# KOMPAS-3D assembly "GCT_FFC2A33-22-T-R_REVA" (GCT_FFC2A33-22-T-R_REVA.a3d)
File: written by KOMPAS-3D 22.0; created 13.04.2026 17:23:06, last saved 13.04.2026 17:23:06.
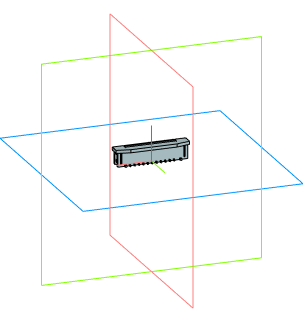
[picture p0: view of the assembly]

Document properties: Автор: Andrey; Полное имя файла: C:\Users\User1\Documents\GCT_FFC2A33-22-T-R_REVA.a3d

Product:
- Component [detail]: 525592253wbm000_01  | qty 1  | source file: 525592253wbm000_01.m3d
- Part/product: GCT_FFC2A33-22-T-R_REVA
    Комментарий: GCT_FFC2A33-22-T-R_REVA

Referenced files in C:\Users\User1\Documents\: 525592253wbm000_01.m3d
